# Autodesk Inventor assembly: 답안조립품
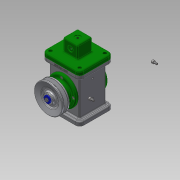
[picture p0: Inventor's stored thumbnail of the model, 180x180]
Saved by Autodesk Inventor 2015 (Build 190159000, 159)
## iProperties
Created: 2017-08
Part Number: 답안조립품
Document SubType Name: Assembly
Designer: Administrator
Author: Administrator
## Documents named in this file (18)
- C:\Users\Administrator\Desktop\470807V1015\답안조립품.iam
- C:\Users\Administrator\Desktop\470807V1015\본체.ipt
- C:\Users\Administrator\Desktop\470807V1015\E-링.ipt
- C:\Users\Administrator\Desktop\470807V1015\V-벨트풀리.ipt
- C:\Users\Administrator\Desktop\470807V1015\덮개.ipt
- C:\Users\Administrator\Desktop\470807V1015\뒤커버.ipt
- C:\Users\Administrator\Desktop\470807V1015\링크.ipt
- C:\Users\Administrator\Desktop\470807V1015\베어링 17 x 40 x 12.ipt
- C:\Users\Administrator\Desktop\470807V1015\볼트 M4 x 8.ipt
- C:\Users\Administrator\Desktop\470807V1015\볼트 M4 x 10.ipt
- C:\Users\Administrator\Desktop\470807V1015\슬라이더.ipt
- C:\Users\Administrator\Desktop\470807V1015\앞커버.ipt
- C:\Users\Administrator\Desktop\470807V1015\오일 실 17 30 8.ipt
- C:\Users\Administrator\Desktop\470807V1015\와셔 4x16.ipt
- C:\Users\Administrator\Desktop\470807V1015\클레비스 핀 6 x 22.ipt
- 클레비스 핀 6 x 22.ipt
- C:\Users\Administrator\Desktop\470807V1015\키 4 x 4 x 12.ipt
- C:\Users\Administrator\Desktop\470807V1015\편심축.ipt
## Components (2 placed, 2 different names)
1. E-링:1
2. V-벨트풀리:1 — 각도:2
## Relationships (1: Angle 1)
- 각도:2 [Angle]: V-벨트풀리:1
